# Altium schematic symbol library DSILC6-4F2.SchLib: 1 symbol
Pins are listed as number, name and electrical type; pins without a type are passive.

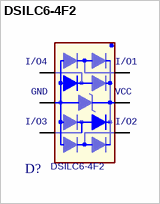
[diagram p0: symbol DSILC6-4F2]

## DSILC6-4F2
designator D?
footprint ST_CSP06N50P3X2_110X157X65
pins: A1 I/O1, A2 I/O4, B1 VCC, B2 GND, C1 I/O2, C2 I/O3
